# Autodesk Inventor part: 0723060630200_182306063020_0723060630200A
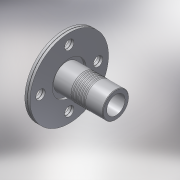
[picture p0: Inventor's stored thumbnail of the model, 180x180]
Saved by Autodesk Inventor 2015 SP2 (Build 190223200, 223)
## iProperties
Created: 2017-02
Part Number: 0723060630200_182306063020_0723060630200A
Material: PVC-Piping
Description: PLASSON FLANGE ADAPTOR WITH METAL FLANGE 63-2"
Document SubType Name: Modeling
Designer: KIM
Mass: 92.6774 g
Surface Area: 199.44 cm^2
Volume: 66.1981 cm^3
Density: 1.4 g/cm^3
Appearance: Smooth - White
Author: KIM
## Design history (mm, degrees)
derived "072306.ipt"
feature "Solid1::072306.ipt"
tag "TaggingFeature1"
body "Solid1"
other parameters: "d73" = 12.4, "d74" = 90 deg, "d75" = 0.3, "d76" = 165, "d77" = 18, "d78" = 62.5, "d80" = 0, "d82" = 360 deg, "d96" = 0.3, "d99" = 360 deg, "d101" = 63, "d102" = 44.1, "d103" = 124, "d104" = 1.26, "d107" = 81.9, "d108" = 3.1, "d109" = 61.74, "d110" = 49.6, "d111" = 6.3, "d115" = 6.3, "d_" = 63, "E_" = 82, "H_" = 124, "D_" = 165, "Dp_" = 125, "S_" = 18
